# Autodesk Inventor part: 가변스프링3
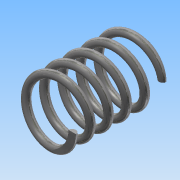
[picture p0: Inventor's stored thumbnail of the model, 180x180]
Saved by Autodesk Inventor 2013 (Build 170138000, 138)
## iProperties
Created: 2014-12
Part Number: 가변스프링3
Material: 강철, 탄소
Document SubType Name: Modeling
Designer: Administrator
Density: 7.87 g/cm^3
Mass: 18.8852 g
Surface Area: 32.5231 cm^2
Volume: 2.39964 cm^3
Author: Administrator
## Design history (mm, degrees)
sketch "스케치1"
  geometry: L1 (0, 0)-(0, 36.261); L2 (0, 36.261)-(11, 36.261); L3 (0, 0)-(11, 0); C1 r 1.5 at (11, 0)
  constraints: 6 end point, 2 parallel, 1 centre point, 1 coincident, 1 perpendicular, 1 vertical
  dimensions: "d0" = 36.2612 distance of L1.start L1.end (derived); "d1" = 11 distance of L1.end L2.end; "d2" = 3 diameter of C1
feature "코일1" sketch "스케치1" pitch "d3" = 10; turns "d5" = 5; dims "d4" = 36.2612 (= d0), "d6" = 0, angle "d7" = 90 deg, angle "d8" = 90 deg, "d9" = 0, "d10" = 0
sketch "스케치2"
  geometry: L1 (36.261, 16.5)-(0, 16.5); L2 (0, 16.5)-(0, -16.5); L3 (0, -16.5)-(36.261, -16.5); L4 (36.261, -16.5)-(36.261, 16.5); 2 further points
  constraints: 8 end point, 2 coincident, 2 parallel, 1 horizontal, 1 midpoint, 1 perpendicular
  dimensions: "d11" = 36.2612 distance of L2.end L3.end (derived); "d13" = 33 distance of L3.end L1.start
extrude "돌출1" sketch "스케치2" stored distance "d14" = 0; taper "d15" = 0 deg
node "솔리드1"
